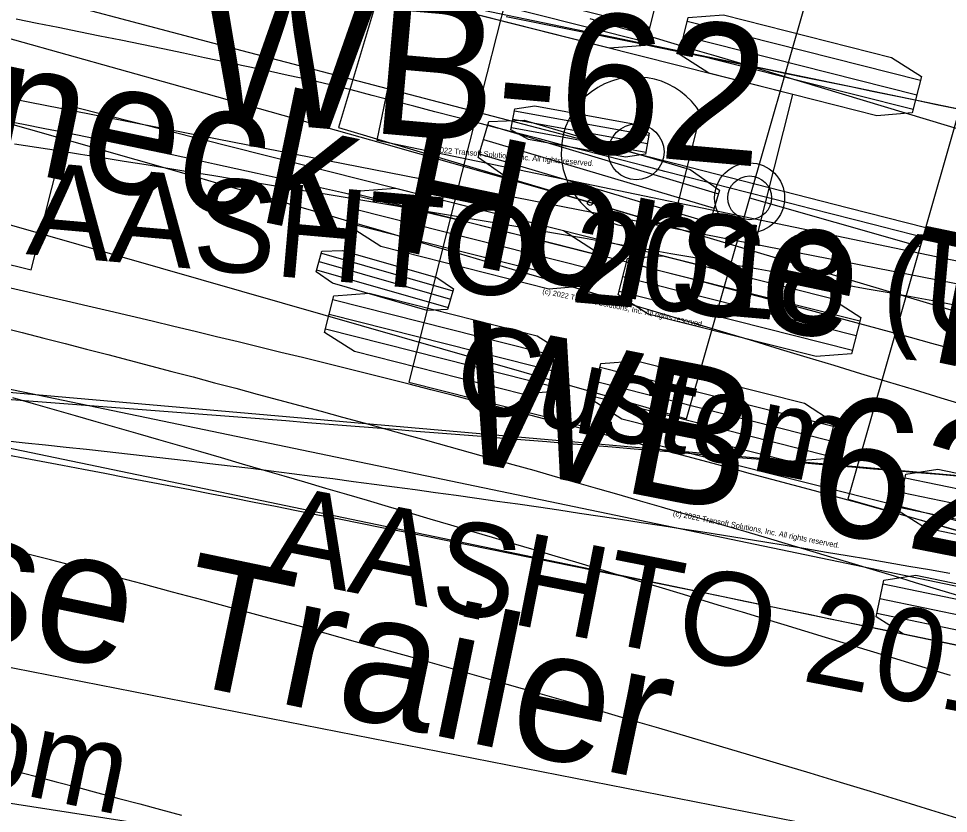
# Model space of a CAD drawing. Extents: x -14 to 1565148, y -25 to 642856.
# Drawn here: x 1565044.63 to 1565058.8, y 636504.76 to 636516.86 of the extents above; entities that cross this region are included whole.
import ezdxf

# ---------------------------------------------------------------- set-up
doc = ezdxf.new("R2010")
doc.units = 0
for name, color, linetype in [('DR_P_Headwall', 7, 'Continuous'), ('GE_P_Alignment_100_Stations', 7, 'Continuous'), ('MT_P_Drums', 7, 'Continuous'), ('MT_P_Work_Area', 7, 'Continuous'), ('PM_P_Edge_Line', 7, 'Continuous'), ('TR_Turning_Path25', 7, 'Continuous'), ('TR_Turning_Path27', 7, 'Continuous'), ('TR_Turning_Path28', 7, 'Continuous'), ('TR_Turning_Path29', 7, 'Continuous')]:
    doc.layers.add(name, color=color, linetype=linetype)

msp = doc.modelspace()

# ---------------------------------------------------------------- linework, layer by layer
at = {"layer": 'DR_P_Headwall'}
for p, q in [((1565054.806, 636510.768), (1565056.734, 636517.497)), ((1565059.468, 636517.234), (1565057.264, 636509.544)), ((1565036.541, 636516.001), (1565054.806, 636510.768)), ((1565055.77, 636514.133), (1565058.366, 636513.389)), ((1565055.77, 636514.133), (1565055.77, 636514.133)), ((1565049.244, 636513.288), (1565051.246, 636512.714)), ((1565049.208, 636513.163), (1565051.21, 636512.589)), ((1565049.172, 636513.038), (1565051.175, 636512.464)), ((1565057.264, 636509.544), (1565083.22, 636502.107)), ((1565057.264, 636509.544), (1565057.264, 636509.544))]:
    msp.add_line(p, q, dxfattribs=at)
msp.add_lwpolyline([(1565049.163, 636513.007), (1565049.252, 636513.319), (1565049.56, 636513.333), (1565051.002, 636512.92), (1565051.255, 636512.745), (1565051.166, 636512.433), (1565050.858, 636512.419), (1565049.416, 636512.832)], close=True, dxfattribs=at)
msp.add_lwpolyline([(1565059.02, 636509.041), (1565058.697, 636509.132), (1565058.374, 636509.223), (1565058.051, 636509.312), (1565057.728, 636509.401), (1565057.404, 636509.49), (1565057.081, 636509.579), (1565056.757, 636509.667), (1565056.433, 636509.756), (1565056.109, 636509.844), (1565055.785, 636509.931), (1565055.46, 636510.019), (1565055.136, 636510.106), (1565054.811, 636510.193), (1565054.487, 636510.279), (1565054.162, 636510.365), (1565053.837, 636510.451), (1565053.512, 636510.537), (1565053.188, 636510.622), (1565052.862, 636510.707), (1565052.537, 636510.792), (1565052.212, 636510.876), (1565051.887, 636510.96), (1565051.561, 636511.043), (1565051.236, 636511.127), (1565050.91, 636511.209), (1565050.584, 636511.292), (1565050.258, 636511.374), (1565049.932, 636511.456), (1565049.606, 636511.537), (1565049.28, 636511.618), (1565048.954, 636511.699), (1565048.628, 636511.779), (1565048.301, 636511.859), (1565047.975, 636511.938), (1565047.648, 636512.017), (1565047.321, 636512.096), (1565046.994, 636512.174), (1565046.667, 636512.252), (1565046.34, 636512.329), (1565046.013, 636512.406), (1565045.686, 636512.483), (1565045.358, 636512.559), (1565045.031, 636512.635), (1565044.703, 636512.71), (1565044.375, 636512.785)], dxfattribs=at)
for radius in [0.533, 0.333]:
    msp.add_circle((1565055.77, 636514.133), radius, dxfattribs=at)
at = {"layer": 'GE_P_Alignment_100_Stations'}
for p, q in [((1565051.789, 636522.869), (1565049.506, 636515.202)), ((1565051.778, 636515.243), (1565055.293, 636514.196)), ((1565049.506, 636515.202), (1565063.882, 636510.921)), ((1565049.506, 636515.202), (1565049.506, 636515.202)), ((1565051.713, 636515.023), (1565055.227, 636513.976)), ((1565051.648, 636514.803), (1565055.162, 636513.757))]:
    msp.add_line(p, q, dxfattribs=at)
for points in [[(1565053.339, 636514.06), (1565050.158, 636514.967), (1565046.964, 636515.866), (1565043.768, 636516.759), (1565040.57, 636517.644), (1565037.371, 636518.524), (1565034.17, 636519.396), (1565030.967, 636520.262), (1565027.762, 636521.121), (1565024.555, 636521.974), (1565021.347, 636522.82), (1565018.137, 636523.659), (1565014.925, 636524.492), (1565011.711, 636525.318), (1565008.496, 636526.137), (1565008.174, 636526.219)], [(1565083.222, 636507.646), (1565079.958, 636508.405), (1565076.712, 636509.174), (1565073.467, 636509.953), (1565070.225, 636510.74), (1565066.985, 636511.535), (1565063.747, 636512.34), (1565060.511, 636513.153), (1565057.277, 636513.974), (1565054.045, 636514.805), (1565050.816, 636515.644), (1565047.589, 636516.491), (1565044.364, 636517.348), (1565041.141, 636518.213), (1565037.921, 636519.086), (1565034.703, 636519.968), (1565032.131, 636520.68)], [(1565058.941, 636513.397), (1565058.622, 636513.477), (1565058.304, 636513.558), (1565057.985, 636513.639), (1565057.666, 636513.72), (1565057.347, 636513.801), (1565057.029, 636513.883), (1565056.71, 636513.964), (1565056.391, 636514.045), (1565056.073, 636514.127), (1565055.754, 636514.209), (1565055.435, 636514.29), (1565055.116, 636514.372), (1565054.798, 636514.454), (1565054.479, 636514.536), (1565054.16, 636514.618), (1565053.842, 636514.7), (1565053.523, 636514.782), (1565053.204, 636514.865), (1565052.885, 636514.947), (1565052.567, 636515.03), (1565052.248, 636515.112), (1565051.929, 636515.195), (1565051.61, 636515.278), (1565051.291, 636515.361), (1565050.972, 636515.444), (1565050.654, 636515.527), (1565050.335, 636515.61), (1565050.016, 636515.693), (1565049.697, 636515.776), (1565049.378, 636515.856), (1565049.059, 636515.929), (1565048.74, 636515.998), (1565048.421, 636516.066), (1565048.102, 636516.134), (1565047.783, 636516.201), (1565047.464, 636516.268), (1565047.145, 636516.335), (1565046.826, 636516.401), (1565046.507, 636516.467), (1565046.188, 636516.533), (1565045.869, 636516.598), (1565045.55, 636516.662), (1565045.231, 636516.727), (1565044.912, 636516.791), (1565044.593, 636516.854)], [(1565058.864, 636511.827), (1565058.544, 636511.915), (1565058.223, 636512.003), (1565057.903, 636512.09), (1565057.583, 636512.177), (1565057.262, 636512.264), (1565056.942, 636512.351), (1565056.622, 636512.437), (1565056.301, 636512.523), (1565055.98, 636512.608), (1565055.66, 636512.693), (1565055.339, 636512.777), (1565055.018, 636512.862), (1565054.698, 636512.945), (1565054.377, 636513.028), (1565054.056, 636513.111), (1565053.735, 636513.193), (1565053.413, 636513.275), (1565053.092, 636513.356), (1565052.771, 636513.437), (1565052.45, 636513.517), (1565052.128, 636513.597), (1565051.807, 636513.676), (1565051.485, 636513.755), (1565051.163, 636513.833), (1565050.841, 636513.91), (1565050.52, 636513.987), (1565050.197, 636514.063), (1565049.875, 636514.138), (1565049.553, 636514.213), (1565049.231, 636514.287), (1565048.908, 636514.361), (1565048.586, 636514.434), (1565048.263, 636514.506), (1565047.94, 636514.577), (1565047.617, 636514.648), (1565047.294, 636514.718), (1565046.971, 636514.787), (1565046.648, 636514.856), (1565046.324, 636514.923), (1565046.001, 636514.99), (1565045.677, 636515.056), (1565045.354, 636515.121), (1565045.03, 636515.186), (1565044.706, 636515.25), (1565044.381, 636515.312)]]:
    msp.add_lwpolyline(points, dxfattribs=at)
msp.add_lwpolyline([(1565051.631, 636514.749), (1565051.795, 636515.297), (1565052.336, 636515.316), (1565054.866, 636514.562), (1565055.309, 636514.25), (1565055.146, 636513.702), (1565054.604, 636513.684), (1565052.074, 636514.437)], close=True, dxfattribs=at)
msp.add_circle((1565053.339, 636514.06), 0.0417, dxfattribs=at)
msp.add_arc((1565365.694, 637720.982), 1241.789, 254.467176, 256.876425, dxfattribs=at)
at = {"layer": 'MT_P_Drums'}
msp.add_line((1565052.956, 636503.602), (1565017.377, 636509.092), dxfattribs=at)
at = {"layer": 'MT_P_Work_Area'}
for p, q in [((1565072.656, 636512.633), (1565037.41, 636519.964)), ((1565035.781, 636512.131), (1565071.027, 636504.801)), ((1565058.139, 636509.869), (1565061.37, 636509.197)), ((1565058.092, 636509.644), (1565061.323, 636508.972)), ((1565058.046, 636509.42), (1565061.277, 636508.748)), ((1565057.803, 636508.253), (1565061.034, 636507.581)), ((1565057.756, 636508.029), (1565060.987, 636507.357)), ((1565057.71, 636507.805), (1565060.941, 636507.133))]:
    msp.add_line(p, q, dxfattribs=at)
for points in [[(1565058.946, 636515.483), (1565058.619, 636515.551), (1565058.292, 636515.619), (1565057.965, 636515.686), (1565057.637, 636515.754), (1565057.31, 636515.822), (1565056.982, 636515.889), (1565056.654, 636515.956), (1565056.327, 636516.024), (1565055.999, 636516.091), (1565055.671, 636516.158), (1565055.343, 636516.225), (1565055.015, 636516.292), (1565054.687, 636516.358), (1565054.359, 636516.425), (1565054.031, 636516.492), (1565053.702, 636516.558), (1565053.374, 636516.624), (1565053.045, 636516.69), (1565052.717, 636516.756), (1565052.388, 636516.822), (1565052.06, 636516.888)], [(1565058.954, 636507.312), (1565058.628, 636507.379), (1565058.301, 636507.447), (1565057.975, 636507.515), (1565057.649, 636507.582), (1565057.324, 636507.65), (1565056.998, 636507.717), (1565056.672, 636507.785), (1565056.346, 636507.852), (1565056.02, 636507.919), (1565055.695, 636507.986), (1565055.369, 636508.053), (1565055.044, 636508.12), (1565054.718, 636508.187), (1565054.393, 636508.254), (1565054.068, 636508.32), (1565053.742, 636508.387), (1565053.417, 636508.453), (1565053.092, 636508.519), (1565052.767, 636508.585), (1565052.441, 636508.651), (1565052.116, 636508.717), (1565051.791, 636508.782), (1565051.466, 636508.848), (1565051.141, 636508.913), (1565050.816, 636508.978), (1565050.491, 636509.043), (1565050.167, 636509.108), (1565049.842, 636509.173), (1565049.517, 636509.237), (1565049.192, 636509.301), (1565048.867, 636509.365), (1565048.543, 636509.429), (1565048.218, 636509.493), (1565047.893, 636509.556), (1565047.569, 636509.619), (1565047.244, 636509.683), (1565046.919, 636509.745), (1565046.595, 636509.808), (1565046.27, 636509.87), (1565045.946, 636509.933), (1565045.621, 636509.995), (1565045.297, 636510.056), (1565044.972, 636510.118), (1565044.648, 636510.179), (1565044.323, 636510.24)]]:
    msp.add_lwpolyline(points, dxfattribs=at)
for points in [[(1565058.034, 636509.364), (1565058.151, 636509.924), (1565058.638, 636509.999), (1565060.964, 636509.515), (1565061.381, 636509.252), (1565061.265, 636508.692), (1565060.778, 636508.618), (1565058.451, 636509.102)], [(1565057.698, 636507.749), (1565057.815, 636508.309), (1565058.302, 636508.384), (1565060.628, 636507.9), (1565061.045, 636507.637), (1565060.929, 636507.077), (1565060.442, 636507.002), (1565058.115, 636507.486)]]:
    msp.add_lwpolyline(points, close=True, dxfattribs=at)
at = {"layer": 'PM_P_Edge_Line'}
for p, q in [((1565051.512, 636521.865), (1565050.088, 636515.012)), ((1565052.185, 636515.459), (1565054.235, 636515.087)), ((1565052.162, 636515.331), (1565054.212, 636514.959)), ((1565052.139, 636515.203), (1565054.188, 636514.83)), ((1565050.088, 636515.012), (1565068.691, 636511.147)), ((1565050.088, 636515.012), (1565050.088, 636515.012))]:
    msp.add_line(p, q, dxfattribs=at)
msp.add_lwpolyline([(1565052.133, 636515.171), (1565052.191, 636515.491), (1565052.495, 636515.535), (1565053.971, 636515.267), (1565054.241, 636515.118), (1565054.183, 636514.799), (1565053.878, 636514.754), (1565052.402, 636515.023)], close=True, dxfattribs=at)
msp.add_lwpolyline([(1565058.892, 636512.5), (1565058.56, 636512.562), (1565058.227, 636512.623), (1565057.895, 636512.684), (1565057.562, 636512.744), (1565057.23, 636512.805), (1565056.898, 636512.865), (1565056.565, 636512.925), (1565056.233, 636512.985), (1565055.9, 636513.045), (1565055.567, 636513.104), (1565055.235, 636513.164), (1565054.902, 636513.223), (1565054.569, 636513.282), (1565054.236, 636513.341), (1565053.904, 636513.399), (1565053.571, 636513.457), (1565053.238, 636513.516), (1565052.905, 636513.574), (1565052.572, 636513.631), (1565052.239, 636513.689), (1565051.906, 636513.746), (1565051.573, 636513.803), (1565051.24, 636513.86), (1565050.907, 636513.917), (1565050.574, 636513.973), (1565050.24, 636514.029), (1565049.907, 636514.085), (1565049.574, 636514.141), (1565049.241, 636514.197), (1565048.907, 636514.252), (1565048.574, 636514.307), (1565048.24, 636514.362), (1565047.907, 636514.417), (1565047.573, 636514.472), (1565047.24, 636514.526), (1565046.906, 636514.58), (1565046.573, 636514.634), (1565046.239, 636514.687), (1565045.905, 636514.741), (1565045.571, 636514.794), (1565045.238, 636514.847), (1565044.904, 636514.9), (1565044.57, 636514.952)], dxfattribs=at)
at = {"layer": 'TR_Turning_Path25'}
msp.add_line((1565061.6, 636507.657), (1565026.354, 636514.984), dxfattribs=at)
for points in [[(1565044.361, 636512.164), (1565044.687, 636512.081), (1565045.013, 636511.997), (1565045.339, 636511.914), (1565045.665, 636511.83), (1565045.99, 636511.745), (1565046.316, 636511.66), (1565046.641, 636511.575), (1565046.966, 636511.489), (1565047.292, 636511.404), (1565047.617, 636511.317), (1565047.942, 636511.231), (1565048.267, 636511.144), (1565048.592, 636511.056), (1565048.916, 636510.969), (1565049.241, 636510.881), (1565049.566, 636510.792), (1565049.89, 636510.704), (1565050.215, 636510.615), (1565050.539, 636510.525), (1565050.863, 636510.436), (1565051.187, 636510.345), (1565051.511, 636510.255), (1565051.835, 636510.164), (1565052.159, 636510.073), (1565052.483, 636509.982), (1565052.806, 636509.89), (1565053.13, 636509.798), (1565053.453, 636509.705), (1565053.777, 636509.612), (1565054.1, 636509.519), (1565054.423, 636509.425), (1565054.746, 636509.331), (1565055.069, 636509.237), (1565055.392, 636509.142), (1565055.714, 636509.048), (1565056.037, 636508.952), (1565056.359, 636508.857), (1565056.682, 636508.76), (1565057.004, 636508.664), (1565057.326, 636508.567), (1565057.648, 636508.47), (1565057.97, 636508.373), (1565058.292, 636508.275), (1565058.614, 636508.177), (1565058.936, 636508.079)], [(1565044.566, 636505.405), (1565044.884, 636505.321), (1565045.203, 636505.238), (1565045.521, 636505.154), (1565045.84, 636505.069), (1565046.158, 636504.985), (1565046.476, 636504.9), (1565046.794, 636504.814), (1565047.113, 636504.728)]]:
    msp.add_lwpolyline(points, dxfattribs=at)
msp.add_arc((1564967.411, 636209.604), 308.945, 69.72175, 81.14322, dxfattribs=at)
at = {"layer": 'TR_Turning_Path27'}
for p, q in [((1565080.683, 636508.555), (1565033.648, 636517.772)), ((1565032.013, 636509.43), (1565079.048, 636500.214))]:
    msp.add_line(p, q, dxfattribs=at)
for points in [[(1565053.333, 636516.865), (1565053.654, 636516.77), (1565053.974, 636516.675), (1565054.295, 636516.58), (1565054.616, 636516.485), (1565054.936, 636516.389), (1565055.257, 636516.294), (1565055.578, 636516.198), (1565055.898, 636516.102), (1565056.219, 636516.007), (1565056.539, 636515.911), (1565056.859, 636515.814), (1565057.18, 636515.718), (1565057.5, 636515.622), (1565057.82, 636515.525), (1565058.141, 636515.428), (1565058.461, 636515.332), (1565058.781, 636515.235), (1565059.101, 636515.137)], [(1565044.536, 636511.093), (1565044.854, 636511.002), (1565045.172, 636510.91), (1565045.491, 636510.819), (1565045.809, 636510.727), (1565046.127, 636510.636), (1565046.445, 636510.544), (1565046.764, 636510.452), (1565047.082, 636510.36), (1565047.4, 636510.268), (1565047.718, 636510.176), (1565048.036, 636510.083), (1565048.354, 636509.99), (1565048.672, 636509.898), (1565048.989, 636509.805), (1565049.307, 636509.712), (1565049.625, 636509.619), (1565049.943, 636509.526), (1565050.26, 636509.432), (1565050.578, 636509.339), (1565050.896, 636509.245), (1565051.213, 636509.151), (1565051.531, 636509.057), (1565051.848, 636508.963), (1565052.166, 636508.869), (1565052.483, 636508.775), (1565052.801, 636508.68), (1565053.118, 636508.586), (1565053.435, 636508.491), (1565053.753, 636508.396), (1565054.07, 636508.301), (1565054.387, 636508.206), (1565054.704, 636508.111), (1565055.021, 636508.015), (1565055.338, 636507.92), (1565055.655, 636507.824), (1565055.972, 636507.728), (1565056.289, 636507.632), (1565056.606, 636507.536), (1565056.923, 636507.44), (1565057.24, 636507.344), (1565057.557, 636507.247), (1565057.874, 636507.151), (1565058.19, 636507.054), (1565058.507, 636506.957), (1565058.824, 636506.86)]]:
    msp.add_lwpolyline(points, dxfattribs=at)
msp.add_arc((1564828.253, 635754.783), 790.626, 70.211484, 74.167159, dxfattribs=at)
at = {"layer": 'TR_Turning_Path28'}
msp.add_line((1565028.277, 636512.594), (1565076.022, 636508.405), dxfattribs=at)
msp.add_lwpolyline([(1565058.986, 636509.888), (1565058.654, 636509.917), (1565058.322, 636509.945), (1565057.99, 636509.973), (1565057.659, 636510.001), (1565057.327, 636510.029), (1565056.995, 636510.057), (1565056.663, 636510.085), (1565056.331, 636510.112), (1565055.999, 636510.14), (1565055.667, 636510.168), (1565055.335, 636510.195), (1565055.003, 636510.223), (1565054.672, 636510.251), (1565054.34, 636510.278), (1565054.008, 636510.305), (1565053.676, 636510.333), (1565053.344, 636510.36), (1565053.013, 636510.387), (1565052.681, 636510.414), (1565052.349, 636510.441), (1565052.017, 636510.468), (1565051.685, 636510.495), (1565051.354, 636510.522), (1565051.022, 636510.549), (1565050.69, 636510.575), (1565050.359, 636510.602), (1565050.027, 636510.628), (1565049.695, 636510.655), (1565049.364, 636510.681), (1565049.032, 636510.707), (1565048.7, 636510.734), (1565048.369, 636510.76), (1565048.037, 636510.786), (1565047.705, 636510.812), (1565047.374, 636510.837), (1565047.042, 636510.863), (1565046.71, 636510.889), (1565046.379, 636510.915), (1565046.047, 636510.94), (1565045.716, 636510.965), (1565045.384, 636510.991), (1565045.053, 636511.016), (1565044.721, 636511.041), (1565044.389, 636511.066)], dxfattribs=at)
at = {"layer": 'TR_Turning_Path29'}
for p, q in [((1565052.659, 636519.564), (1565051.618, 636515.444)), ((1565056.429, 636515.707), (1565046.152, 636518.302)), ((1565050.692, 636517.629), (1565054.247, 636516.731)), ((1565050.636, 636517.406), (1565054.191, 636516.509)), ((1565054.82, 636516.823), (1565058.375, 636515.925)), ((1565030.278, 636516.705), (1565044.822, 636513.034)), ((1565054.764, 636516.601), (1565058.319, 636515.703)), ((1565054.708, 636516.378), (1565058.263, 636515.481)), ((1565055.728, 636512.928), (1565056.429, 636515.707)), ((1565044.822, 636513.034), (1565045.45, 636515.523)), ((1565045.45, 636515.523), (1565055.728, 636512.928)), ((1565051.618, 636515.444), (1565050.578, 636511.323)), ((1565054.628, 636513.85), (1565055.024, 636515.417)), ((1565049.822, 636514.183), (1565053.377, 636513.285)), ((1565049.766, 636513.96), (1565053.321, 636513.063)), ((1565049.71, 636513.738), (1565053.265, 636512.841)), ((1565053.894, 636513.155), (1565057.449, 636512.257)), ((1565053.838, 636512.932), (1565057.393, 636512.035)), ((1565053.782, 636512.71), (1565057.337, 636511.813)), ((1565049.418, 636512.583), (1565052.973, 636511.685)), ((1565049.362, 636512.361), (1565052.917, 636511.463)), ((1565049.306, 636512.138), (1565052.861, 636511.241)), ((1565053.49, 636511.555), (1565057.045, 636510.657)), ((1565050.578, 636511.323), (1565097.05, 636499.591)), ((1565053.434, 636511.333), (1565056.989, 636510.435)), ((1565053.378, 636511.11), (1565056.933, 636510.213))]:
    msp.add_line(p, q, dxfattribs=at)
for points in [[(1565050.622, 636517.351), (1565050.762, 636517.906), (1565051.302, 636517.947), (1565053.861, 636517.301), (1565054.317, 636517.008), (1565054.177, 636516.454), (1565053.637, 636516.412), (1565051.077, 636517.059)], [(1565054.694, 636516.323), (1565054.834, 636516.878), (1565055.374, 636516.919), (1565057.934, 636516.273), (1565058.389, 636515.98), (1565058.249, 636515.426), (1565057.709, 636515.384), (1565055.15, 636516.031)], [(1565049.696, 636513.683), (1565049.836, 636514.238), (1565050.376, 636514.279), (1565052.935, 636513.633), (1565053.391, 636513.34), (1565053.251, 636512.786), (1565052.711, 636512.744), (1565050.151, 636513.39)], [(1565053.768, 636512.655), (1565053.908, 636513.21), (1565054.448, 636513.251), (1565057.008, 636512.605), (1565057.463, 636512.312), (1565057.323, 636511.758), (1565056.783, 636511.716), (1565054.224, 636512.362)], [(1565049.292, 636512.083), (1565049.432, 636512.638), (1565049.972, 636512.679), (1565052.531, 636512.033), (1565052.987, 636511.74), (1565052.847, 636511.186), (1565052.307, 636511.144), (1565049.747, 636511.79)], [(1565053.364, 636511.055), (1565053.504, 636511.61), (1565054.044, 636511.651), (1565056.604, 636511.005), (1565057.059, 636510.712), (1565056.919, 636510.158), (1565056.379, 636510.116), (1565053.82, 636510.762)]]:
    msp.add_lwpolyline(points, close=True, dxfattribs=at)
msp.add_lwpolyline([(1565058.823, 636508.41), (1565058.509, 636508.465), (1565058.195, 636508.519), (1565057.881, 636508.573), (1565057.568, 636508.627), (1565057.254, 636508.68), (1565056.94, 636508.732), (1565056.626, 636508.784), (1565056.313, 636508.836), (1565055.999, 636508.887), (1565055.686, 636508.938), (1565055.372, 636508.988), (1565055.058, 636509.038), (1565054.745, 636509.087), (1565054.431, 636509.136), (1565054.118, 636509.184), (1565053.804, 636509.232), (1565053.491, 636509.279), (1565053.178, 636509.326), (1565052.864, 636509.373), (1565052.551, 636509.419), (1565052.238, 636509.464), (1565051.924, 636509.509), (1565051.611, 636509.553), (1565051.298, 636509.597), (1565050.985, 636509.64), (1565050.672, 636509.683), (1565050.359, 636509.726), (1565050.046, 636509.767), (1565049.732, 636509.809), (1565049.419, 636509.85), (1565049.106, 636509.89), (1565048.793, 636509.93), (1565048.481, 636509.969), (1565048.168, 636510.008), (1565047.855, 636510.046), (1565047.542, 636510.083), (1565047.229, 636510.121), (1565046.916, 636510.157), (1565046.604, 636510.193), (1565046.291, 636510.229), (1565045.978, 636510.264), (1565045.665, 636510.298), (1565045.353, 636510.332), (1565045.04, 636510.365), (1565044.728, 636510.398), (1565044.415, 636510.431)], dxfattribs=at)
msp.add_circle((1565054.042, 636514.832), 0.424, dxfattribs=at)
msp.add_arc((1565054.042, 636514.832), 1.143, 30.8318, 300.8318, dxfattribs=at)

# ---------------------------------------------------------------- texts
at = {"layer": 'MT_P_Drums'}
msp.add_text('Gooseneck Horse Trailer', height=2, rotation=351.2276, dxfattribs=at).set_placement((1565016.462, 636505.348))
at = {"layer": 'MT_P_Work_Area'}
for s, height, p in [('Gooseneck Horse Trailer', 2, (1565036.302, 636516.272)), ('(c) 2022 Transoft Solutions, Inc. All rights reserved.', 0.08, (1565052.607, 636512.677)), ('Custom', 1.3333, (1565051.199, 636510.961))]:
    msp.add_text(s, height=height, rotation=348.2502, dxfattribs=at).set_placement(p)
at = {"layer": 'TR_Turning_Path25'}
for s, height, p in [('Gooseneck Horse Trailer', 2, (1565025.246, 636511.292)), ('Custom', 1.3333, (1565040.144, 636505.982))]:
    msp.add_text(s, height=height, rotation=348.2571, dxfattribs=at).set_placement(p)
at = {"layer": 'TR_Turning_Path27'}
for s, height, p in [('WB-62', 2.125, (1565051.133, 636510.188)), ('AASHTO 2018 (US)', 1.41667, (1565048.381, 636508.381)), ('(c) 2022 Transoft Solutions, Inc. All rights reserved.', 0.085, (1565054.597, 636509.292))]:
    msp.add_text(s, height=height, rotation=348.9135, dxfattribs=at).set_placement(p)
at = {"layer": 'TR_Turning_Path28'}
for s, height, p in [('WB-62', 2.125, (1565047.279, 636515.364)), ('(c) 2022 Transoft Solutions, Inc. All rights reserved.', 0.085, (1565050.819, 636514.84)), ('AASHTO 2018 (US)', 1.41667, (1565044.734, 636513.276))]:
    msp.add_text(s, height=height, rotation=354.9852, dxfattribs=at).set_placement(p)

doc.saveas('drawing.dxf')
